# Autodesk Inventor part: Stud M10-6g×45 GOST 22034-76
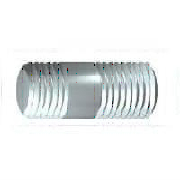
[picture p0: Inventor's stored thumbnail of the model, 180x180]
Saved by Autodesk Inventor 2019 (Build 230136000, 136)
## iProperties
Created: 2018-01
Part Number: Stud M10-6g×45 GOST 22034-76
Material: Steel, Mild
Description: Studs with threaded end of 1.25d, product grade B
Document SubType Name: Modeling
Standard: GOST 22034-76
Designer: m.vorobev
Standards Organization: GOST
Language: en-US
Size Designation: M10-6g×45
Categories: <MemberInstance><Categories><Category DisplayName="Fasteners" InternalName="e4da775c-781d-43d5-af7c-5136215cf5a6" Mnemonic="FSTN"><Category DisplayName="Bolts"
Density: 7.85 g/cm^3
Appearance: Semi-Polished
IsCustomPart: 0
Title: Шпилька
Author: m.vorobev
Keywords: SERIES 1
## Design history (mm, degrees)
sketch "Sketch1"
  geometry: L1 (0, 0)-(0, 5); L2 (0, 5)-(12, 5); L3 (12, 5)-(12, 5); L4 (12, 5)-(31, 5); L5 (31, 5)-(31, 5); L6 (31, 5)-(57, 5); L7 (57, 5)-(57, 0); L8 (57, 0)-(0, 0)
  constraints: 16 end point, 4 parallel, 3 collinear, 1 perpendicular, 1 vertical
  dimensions: "d1" = 10 diameter of L2 L8 (= d); "d3" = 10 diameter of L4 L8 (= d1_); "d4" = 12 distance of L1.end L2.end (= b1); "d5" = 45 distance between parallel lines of L7 L3 (= L); "d6" = 26 distance of L5.end L6.end (= b)
revolve "Revolution1" sketch "Sketch1" stored, may be unused: angle "d7" = 90 deg
thread "Thread1" dims "d8" = 12 (= d4), "d9" = 0
body "Solid1"
thread "Thread2" dims "d23" = 26 (= b), "d24" = 0
chamfer "Chamfer1" distance "d25" = 0.6 (= chamfer); stored, may be unused: second distance "d26" = 2, angle "d27" = 45 deg
workplane "Work Plane1"
sketch "Sketch2"
  geometry: C1 r 5 at (0, 0); 1 further point
  constraints: 1 centre point, 1 coincident
  dimensions: "d29" = 10 diameter of C1 (= d)
body "Srf1"
patch "Boundary Patch1"
other parameters: "chamfer" = 0.6 [user parameter; used in 1 equation term], "d" = 10 [user parameter; used in 2 equation terms], "d1_" = 10 [user parameter; used in 1 equation term], "b1" = 12 [user parameter; used in 2 equation terms], "L" = 45 [user parameter; used in 1 equation term], "b" = 26 [user parameter; used in 2 equation terms], "d28" = -12 (= -b1), "d32" = 0, "d34" = 0, "Grip_Length" = 19 [user parameter]
